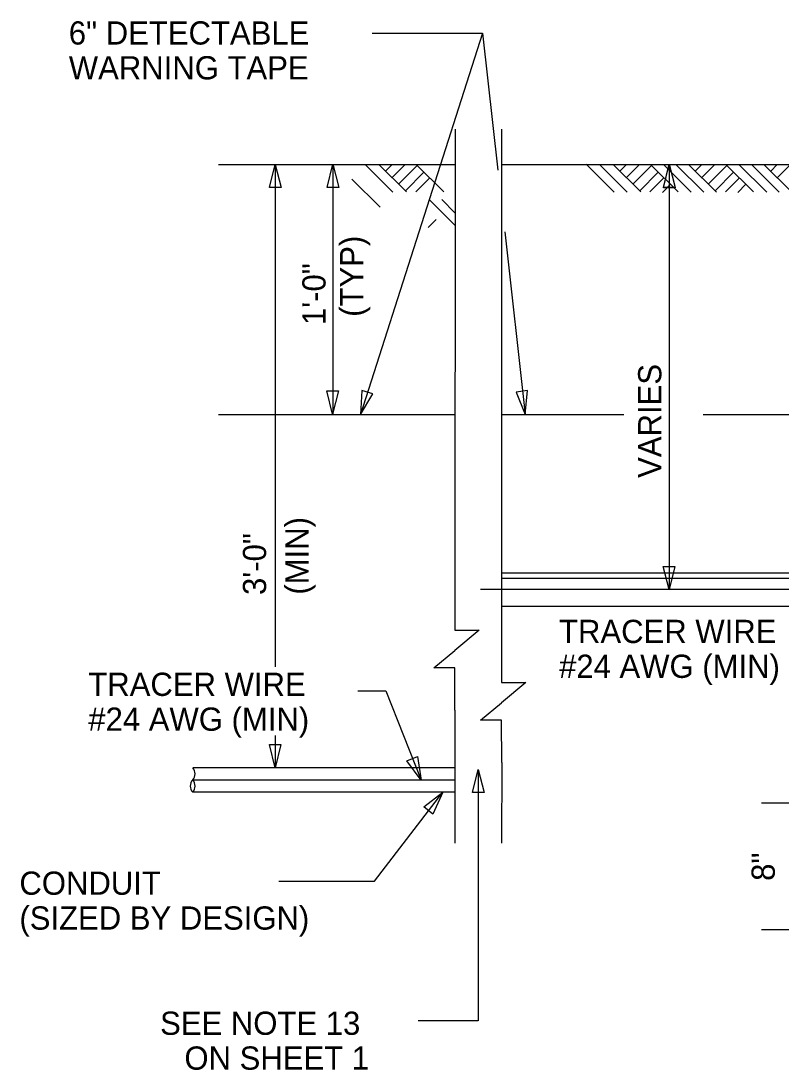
# Model space of a CAD drawing. Extents: x 1299104.8 to 1299141.6, y 239639.8 to 239661.8.
# Drawn here: x 1299120.54 to 1299124.47, y 239646.18 to 239651.6 of the extents above; entities that cross this region are included whole.
import ezdxf

# ---------------------------------------------------------------- set-up
doc = ezdxf.new("R2010")
doc.units = 0
doc.layers.add('DIM TXT', color=7, linetype='Continuous')

msp = doc.modelspace()

# ---------------------------------------------------------------- linework, layer by layer
at = {"layer": 'DIM TXT'}
for p, q in [((1299122.9247, 239651.5387), (1299122.2938, 239649.5699)), ((1299122.7829, 239651.0437), (1299122.7805, 239648.5345)), ((1299123.0217, 239651.0437), (1299123.0217, 239648.2643)), ((1299121.5598, 239650.8613), (1299122.7813, 239650.8613)), ((1299121.853, 239650.8613), (1299121.8533, 239648.2662)), ((1299122.1506, 239650.8613), (1299122.1506, 239649.5699)), ((1299122.4614, 239650.7184), (1299122.3174, 239650.8613)), ((1299122.5319, 239650.7187), (1299122.3882, 239650.8613)), ((1299122.4573, 239650.8613), (1299122.423, 239650.8267)), ((1299122.5247, 239650.8613), (1299122.4574, 239650.7934)), ((1299122.5863, 239650.8563), (1299122.4902, 239650.7594)), ((1299122.7242, 239650.7194), (1299122.5813, 239650.8613)), ((1299123.0213, 239650.8613), (1299123.9914, 239650.8613)), ((1299123.6049, 239650.7182), (1299123.459, 239650.8631)), ((1299123.6718, 239650.7184), (1299123.5278, 239650.8613)), ((1299123.7423, 239650.7187), (1299123.5987, 239650.8613)), ((1299123.6677, 239650.8613), (1299123.6335, 239650.8267)), ((1299123.7351, 239650.8613), (1299123.6678, 239650.7934)), ((1299123.7967, 239650.8563), (1299123.7006, 239650.7594)), ((1299123.9346, 239650.7194), (1299123.7917, 239650.8613)), ((1299124.003, 239650.7182), (1299123.8588, 239650.8613)), ((1299123.8877, 239650.8613), (1299123.888, 239648.6647)), ((1299124.0678, 239650.7182), (1299123.9236, 239650.8613)), ((1299124.1327, 239650.7182), (1299123.9885, 239650.8613)), ((1299123.9914, 239650.8613), (1299125.3906, 239650.8613)), ((1299124.0576, 239650.8613), (1299124.0233, 239650.8267)), ((1299124.125, 239650.8613), (1299124.0577, 239650.7934)), ((1299124.1866, 239650.8563), (1299124.0904, 239650.7594)), ((1299124.3244, 239650.7194), (1299124.1816, 239650.8613)), ((1299124.3928, 239650.7182), (1299124.2486, 239650.8613)), ((1299124.4577, 239650.7182), (1299124.3135, 239650.8613)), ((1299124.5226, 239650.7182), (1299124.3784, 239650.8613)), ((1299124.4474, 239650.8613), (1299124.4132, 239650.8267)), ((1299124.5148, 239650.8613), (1299124.4475, 239650.7934)), ((1299122.3944, 239650.64), (1299122.2485, 239650.7849)), ((1299122.6213, 239650.8216), (1299122.5259, 239650.7254)), ((1299122.6512, 239650.7919), (1299122.5787, 239650.7189)), ((1299123.8317, 239650.8215), (1299123.7363, 239650.7254)), ((1299123.8616, 239650.7919), (1299123.7891, 239650.7189)), ((1299124.2216, 239650.8215), (1299124.1261, 239650.7254)), ((1299124.2514, 239650.7919), (1299124.1789, 239650.7189)), ((1299123.8951, 239650.7586), (1299123.8537, 239650.7169)), ((1299124.2849, 239650.7586), (1299124.2436, 239650.7169)), ((1299122.7814, 239650.5473), (1299122.6485, 239650.6792)), ((1299122.7816, 239650.6115), (1299122.7134, 239650.6792)), ((1299122.6848, 239650.5765), (1299122.6435, 239650.5348)), ((1299121.5597, 239649.5699), (1299122.7812, 239649.5699)), ((1299123.0212, 239649.5699), (1299123.6551, 239649.5699)), ((1299124.0638, 239649.5699), (1299125.3013, 239649.5699)), ((1299123.0217, 239648.7524), (1299125.3022, 239648.7501)), ((1299123.0217, 239648.7234), (1299126.1065, 239648.7237)), ((1299122.7803, 239648.7166), (1299122.7809, 239648.4549)), ((1299132.1436, 239648.6647), (1299122.9138, 239648.6647)), ((1299123.0217, 239648.5795), (1299125.3013, 239648.5793)), ((1299122.7809, 239648.4549), (1299122.9068, 239648.4552)), ((1299122.9068, 239648.4552), (1299122.7811, 239648.3509)), ((1299123.0215, 239648.4464), (1299123.0221, 239648.1846)), ((1299122.672, 239648.2603), (1299122.7811, 239648.3509)), ((1299122.7814, 239648.2606), (1299122.672, 239648.2603)), ((1299122.7819, 239648.0424), (1299122.7814, 239648.2606)), ((1299123.0221, 239648.1846), (1299123.1481, 239648.1849)), ((1299123.1481, 239648.1849), (1299123.0224, 239648.0806)), ((1299122.9133, 239647.99), (1299123.0224, 239648.0806)), ((1299122.7815, 239648.0424), (1299122.7815, 239647.3558)), ((1299123.0226, 239647.9903), (1299122.9133, 239647.99)), ((1299123.0231, 239647.7722), (1299123.0226, 239647.9903)), ((1299121.8534, 239647.9119), (1299121.8534, 239647.7444)), ((1299122.7815, 239647.7444), (1299121.4266, 239647.7444)), ((1299123.0231, 239647.7722), (1299123.0215, 239647.3558)), ((1299122.7815, 239647.6798), (1299121.4266, 239647.6798)), ((1299122.7815, 239647.619), (1299121.4266, 239647.619)), ((1299124.6664, 239647.5623), (1299124.3658, 239647.5623)), ((1299124.6664, 239646.9075), (1299124.3658, 239646.9075))]:
    msp.add_line(p, q, dxfattribs=at)
for points in [[(1299122.3532, 239651.5387), (1299122.9247, 239651.5387), (1299123.0038, 239650.8315)], [(1299123.0395, 239650.5125), (1299123.145, 239649.5699)], [(1299122.2794, 239648.1415), (1299122.4241, 239648.1415), (1299122.6073, 239647.6798)], [(1299122.902, 239647.7364), (1299122.902, 239646.4381), (1299122.5919, 239646.4381)], [(1299121.8716, 239647.1587), (1299122.3652, 239647.1587), (1299122.719, 239647.619)]]:
    msp.add_lwpolyline(points, dxfattribs=at)
for points in [[(1299121.8237, 239650.7411), (1299121.853, 239650.8613), (1299121.8837, 239650.7414)], [(1299122.1214, 239650.7416), (1299122.1507, 239650.8618), (1299122.1814, 239650.742)], [(1299123.859, 239650.7416), (1299123.8883, 239650.8618), (1299123.919, 239650.742)], [(1299123.8593, 239650.7401), (1299123.8887, 239650.8603), (1299123.9193, 239650.7404)], [(1299122.1792, 239649.6917), (1299122.1498, 239649.5715), (1299122.1192, 239649.6914)], [(1299122.3001, 239649.6934), (1299122.2938, 239649.5699), (1299122.3575, 239649.6759)], [(1299123.0975, 239649.6844), (1299123.1443, 239649.5699), (1299123.1569, 239649.6929)], [(1299123.9174, 239648.7849), (1299123.888, 239648.6647), (1299123.8574, 239648.7845)], [(1299121.8827, 239647.8645), (1299121.8534, 239647.7444), (1299121.8227, 239647.8642)], [(1299122.5885, 239647.803), (1299122.6071, 239647.6807), (1299122.5331, 239647.7799)], [(1299122.8726, 239647.6162), (1299122.902, 239647.7364), (1299122.9326, 239647.6166)], [(1299122.6204, 239647.5429), (1299122.7182, 239647.6186), (1299122.6676, 239647.5058)]]:
    msp.add_lwpolyline(points, close=True, dxfattribs=at)
for centre, start, end in [((1299121.3937, 239647.713), 316.3972, 43.6028), ((1299121.4596, 239647.6503), 136.3972, 223.6028), ((1299121.3937, 239647.6503), 316.3972, 43.6028)]:
    msp.add_arc(centre, 0.0455, start, end, dxfattribs=at)

# ---------------------------------------------------------------- texts
for s, p in [('6" DETECTABLE ', (1299120.7864, 239651.4802)), ('WARNING TAPE', (1299120.7864, 239651.3002)), ('TRACER WIRE', (1299123.3196, 239648.3889)), ('#24 AWG (MIN)', (1299123.3196, 239648.2089)), ('TRACER WIRE', (1299120.8872, 239648.1158)), ('#24 AWG (MIN)', (1299120.8872, 239647.9358)), ('CONDUIT ', (1299120.5311, 239647.0886)), ('(SIZED BY DESIGN)', (1299120.5311, 239646.9086)), ('SEE NOTE 13', (1299121.2581, 239646.3652)), ('ON SHEET 1', (1299121.3838, 239646.1852))]:
    msp.add_text(s, height=0.12, dxfattribs=at).set_placement(p)
for s, p in [('(TYP)', (1299122.3079, 239650.0738)), ('1\'-0"', (1299122.1131, 239650.0313)), ('VARIES', (1299123.8481, 239649.2419)), ('(MIN)', (1299122.0252, 239648.6389)), ('3\'-0"', (1299121.806, 239648.6371)), ('8"', (1299124.4343, 239647.1605))]:
    msp.add_text(s, height=0.12, rotation=90, dxfattribs=at).set_placement(p)

doc.saveas('drawing.dxf')
